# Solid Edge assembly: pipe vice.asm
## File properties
Author: CADCIM
Template: Iso Assembly.asm
Last saved by: TIET
Revision: 2
Application: Solid Edge
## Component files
base.par
Screw.par
moveable jaw.par
handle.par
handle screw.par
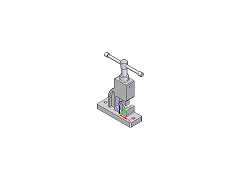
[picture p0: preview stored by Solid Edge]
